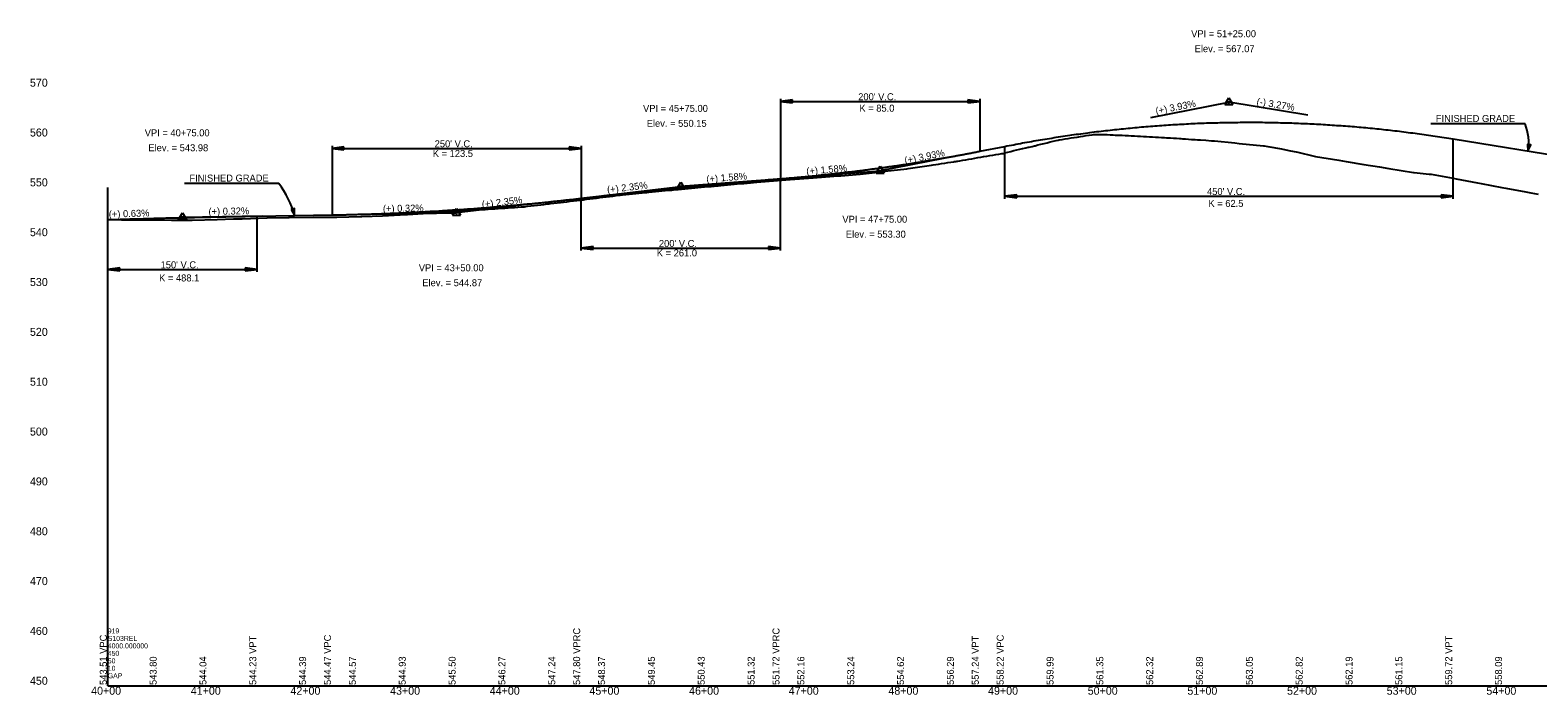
# Model space of a CAD drawing. Extents: x 49922 to 54713, y 49991 to 62800.
# Drawn here: x 49922 to 51435, y 61991 to 62658 of the extents above; entities that cross this region are included whole.
import ezdxf

# ---------------------------------------------------------------- set-up
doc = ezdxf.new("R2010")
doc.units = 0
for name, color, linetype in [('RD_DDB_ElevTX', 7, 'Continuous'), ('RD_DDB_GradeTX', 7, 'Continuous'), ('RD_DDB_Profile_EX', 7, 'Continuous'), ('RD_DDB_Profile_Lbl', 7, 'Continuous'), ('RD_DDB_Profile_PR', 7, 'Continuous'), ('RD_DDB_StaTX', 7, 'Continuous'), ('RD_DDB_StripGrade', 7, 'Continuous'), ('RD_DDB_VCLbl', 7, 'Continuous'), ('RD_GPK_Profile_Cell', 7, 'Continuous'), ('RD_TX_Profile', 7, 'Continuous')]:
    doc.layers.add(name, color=color, linetype=linetype)

msp = doc.modelspace()

# ---------------------------------------------------------------- linework, layer by layer
at = {"layer": 'RD_DDB_GradeTX'}
for p, q in [((51121, 62583.1), (51125, 62589.9)), ((51125, 62589.9), (51129, 62583.1)), ((51046.5, 62569.9), (51125, 62585.3)), ((51121, 62583.1), (51129, 62583.1)), ((51204, 62572.5), (51125, 62585.3)), ((50853.5, 62532), (50775, 62516.5)), ((50695.2, 62510.2), (50775, 62516.5)), ((50771, 62514.2), (50775, 62521.1)), ((50771, 62514.2), (50779, 62514.2)), ((50775, 62521.1), (50779, 62514.2)), ((50495.5, 62491.4), (50575, 62500.7)), ((50571, 62498.4), (50575, 62505.3)), ((50571, 62498.4), (50579, 62498.4)), ((50654.8, 62507), (50575, 62500.7)), ((50575, 62505.3), (50579, 62498.4)), ((50429.5, 62483.7), (50350, 62474.3)), ((50000, 62467.6), (50075, 62469.9)), ((50071, 62467.6), (50075, 62474.5)), ((50071, 62467.6), (50079, 62467.6)), ((50075, 62474.5), (50079, 62467.6)), ((50155, 62471.2), (50075, 62469.9)), ((50270, 62473.1), (50350, 62474.3)), ((50346, 62472), (50350, 62478.9)), ((50346, 62472), (50354, 62472)), ((50350, 62478.9), (50354, 62472))]:
    msp.add_line(p, q, dxfattribs=at)
for centre in [(51125, 62585.3), (50775, 62516.5), (50575, 62500.7), (50075, 62469.9), (50350, 62474.3)]:
    msp.add_circle(centre, 0.529, dxfattribs=at)
at = {"layer": 'RD_DDB_Profile_EX'}
for points in [[(50546.2, 62495.4), (50549.5, 62495.8), (50552.8, 62496.1), (50556.1, 62496.4), (50559.3, 62496.7), (50563.1, 62497.1), (50564, 62497.2), (50565.9, 62497.3), (50569.2, 62497.7), (50572.5, 62498), (50575.8, 62498.3), (50579.1, 62498.6), (50582.3, 62498.9), (50585.6, 62499.2), (50588.2, 62499.4), (50588.9, 62499.5), (50592.2, 62499.8), (50595.5, 62500.1), (50598.8, 62500.4), (50602.1, 62500.7), (50605.4, 62501), (50608.6, 62501.3), (50612.1, 62501.6), (50612.6, 62501.6), (50615.2, 62501.9), (50618.5, 62502.2), (50621.8, 62502.5), (50625.2, 62502.8), (50628.4, 62503.1), (50631.7, 62503.4), (50634.9, 62503.7), (50637.3, 62503.9), (50638.2, 62504), (50641.5, 62504.2), (50644.8, 62504.5), (50651.3, 62505.1), (50659.8, 62505.8), (50684.8, 62507.7), (50707.8, 62509.5), (50732.8, 62511.5), (50735.7, 62511.7), (50754.8, 62513.2), (50779.1, 62516), (50779.8, 62516.1), (50801.9, 62518.7), (50803, 62518.9), (50826.6, 62522.4), (50828.1, 62522.6), (50833.7, 62523.4), (50836.7, 62523.9), (50839.8, 62524.3), (50842.8, 62524.8), (50845.8, 62525.2), (50848.8, 62525.7), (50849.4, 62525.8), (50850.9, 62526), (50851.9, 62526.1), (50852.8, 62526.3), (50854.9, 62526.7), (50857.9, 62527.2), (50860.9, 62527.7), (50863.9, 62528.2), (50867, 62528.7), (50870, 62529.3), (50873, 62529.8), (50876, 62530.3), (50878.7, 62530.8), (50879, 62530.8), (50882.1, 62531.3), (50885.1, 62531.8), (50888.1, 62532.3), (50891.1, 62532.8), (50894.1, 62533.3), (50897.2, 62533.9), (50898.5, 62534.1), (50900.2, 62534.5), (50903.2, 62535.3), (50906.2, 62536), (50909.3, 62536.8), (50912.3, 62537.5), (50915.3, 62538.3), (50917.7, 62538.9), (50918.3, 62539), (50921.3, 62539.7), (50923.5, 62540.2), (50924.4, 62540.4), (50927.4, 62541.1), (50929.9, 62541.7), (50930.4, 62541.8), (50933.4, 62542.6), (50936.4, 62543.3), (50939.5, 62544), (50942.5, 62544.8), (50945.6, 62545.5), (50948.5, 62546.2), (50951.5, 62546.9), (50953.6, 62547.4), (50954.6, 62547.5), (50957.6, 62548), (50960.6, 62548.5), (50963.6, 62549)], [(50963.6, 62549), (50966.7, 62549.5), (50969.2, 62549.9), (50969.7, 62550), (50972.7, 62550.4), (50976, 62550.9), (50978.7, 62551.4), (50981.8, 62551.9), (50984.8, 62552.4), (50987.8, 62552.8), (50989.2, 62553), (50990.8, 62553.1), (50991.5, 62553.1), (50993.8, 62553.1), (50995.4, 62553), (50996.9, 62553), (50999.9, 62553), (51001.8, 62552.9), (51002.9, 62552.9), (51005.9, 62552.7), (51008.9, 62552.6), (51010.7, 62552.5), (51012, 62552.4), (51015, 62552.3), (51018, 62552.2), (51021, 62552), (51024.1, 62551.9), (51026.8, 62551.7), (51027.1, 62551.7), (51030.1, 62551.6), (51033.1, 62551.4), (51035.6, 62551.3), (51036.1, 62551.2), (51039.2, 62551.1), (51042.2, 62550.9), (51045.2, 62550.8), (51048.2, 62550.6), (51051.2, 62550.4), (51051.8, 62550.4), (51054.3, 62550.3), (51057.3, 62550.1), (51060.3, 62549.9), (51062.2, 62549.8), (51063.3, 62549.7), (51066.3, 62549.5), (51069.4, 62549.3), (51072.4, 62549.2), (51075.4, 62549), (51076.8, 62548.9), (51078.4, 62548.8), (51081.5, 62548.6), (51084.5, 62548.4), (51087.5, 62548.1), (51090.5, 62547.9), (51091, 62547.9), (51093.5, 62547.7), (51096.6, 62547.5), (51101.8, 62547.2), (51107.5, 62546.7), (51110.4, 62546.5), (51130.8, 62544.5), (51135.3, 62544), (51159.6, 62541.5), (51160.2, 62541.5), (51164.1, 62541.1), (51177.8, 62538.7), (51185.2, 62537.1), (51194.2, 62535.3), (51210.5, 62531.3), (51211.7, 62531), (51235.2, 62527.1), (51242.6, 62525.9), (51260.2, 62523), (51276, 62520.5), (51285.3, 62518.9), (51310.3, 62514.9), (51310.7, 62514.8), (51325.9, 62513.3), (51328, 62513.1), (51349.9, 62509.1), (51353, 62508.5), (51374.4, 62504.5), (51378, 62503.9), (51398.8, 62500), (51403, 62499.2), (51423, 62495.5), (51428, 62494.5), (51435.2, 62493.2)], [(50000, 62467.6), (50013.9, 62467.5), (50014.6, 62467.5), (50038.9, 62467.3), (50039.6, 62467.3), (50063.9, 62467.1), (50084.2, 62467), (50084.6, 62467), (50109.6, 62467.8), (50126.3, 62468.3), (50134.7, 62468.5), (50159.6, 62469.3), (50160, 62469.3), (50181.3, 62469.9), (50181.9, 62469.9), (50206.3, 62470), (50207, 62470), (50228.9, 62470.1), (50229.9, 62470.1), (50253.9, 62470.9), (50254.9, 62470.9), (50275.6, 62471.5), (50299.4, 62472.9), (50300.6, 62472.9), (50321.7, 62474.1), (50322.7, 62474.1), (50345.8, 62475.6), (50347.7, 62475.8), (50349, 62475.8), (50352.3, 62476.1), (50355.5, 62476.3), (50358.8, 62476.5), (50362.1, 62476.7), (50365.4, 62476.9), (50368, 62477.1), (50368.7, 62477.2), (50370.1, 62477.3), (50372, 62477.4), (50372.5, 62477.5), (50375.3, 62477.7), (50378.6, 62477.9), (50381.8, 62478.1), (50385.1, 62478.3), (50388.4, 62478.5), (50391.7, 62478.8), (50395.1, 62479), (50398.3, 62479.2), (50401.6, 62479.4), (50404.8, 62479.7), (50408.1, 62479.9), (50411.4, 62480.1), (50414.7, 62480.4), (50416.3, 62480.5), (50418, 62480.6), (50419.5, 62480.8), (50421.3, 62481), (50424.6, 62481.4), (50427.9, 62481.8), (50431.1, 62482.1), (50434.4, 62482.5), (50437.7, 62482.9), (50441, 62483.3), (50442.9, 62483.5), (50444.3, 62483.7), (50447.6, 62484), (50450.9, 62484.4), (50454.2, 62484.8), (50457.4, 62485.2), (50460.7, 62485.6), (50464, 62486), (50467.3, 62486.4), (50470.6, 62486.8), (50473.9, 62487.2), (50477.2, 62487.6), (50480.4, 62488), (50483.7, 62488.5), (50486.5, 62488.8), (50487, 62488.9), (50490.3, 62489.3), (50492.3, 62489.5), (50493.6, 62489.7), (50496.9, 62490.1), (50500.2, 62490.5), (50503.5, 62490.9), (50506.7, 62491.3), (50510, 62491.7), (50513.3, 62492.1), (50514.2, 62492.2), (50515.7, 62492.4), (50516.6, 62492.5), (50519.9, 62492.8), (50523.2, 62493.1), (50526.5, 62493.5), (50529.8, 62493.8), (50533, 62494.1), (50536.3, 62494.5), (50539.6, 62494.8), (50540.3, 62494.9), (50540.9, 62494.9), (50542.9, 62495.1), (50546.2, 62495.4)]]:
    msp.add_lwpolyline(points, dxfattribs=at)
at = {"layer": 'RD_DDB_Profile_PR'}
for p, q in [((51350, 62548.6), (51500, 62524.1)), ((50875, 62536.2), (50900, 62541.1)), ((50150, 62471.1), (50225, 62472.3))]:
    msp.add_line(p, q, dxfattribs=at)
for points in [[(50900, 62541.1), (50909, 62542.8), (50918, 62544.5), (50927, 62546.1), (50936, 62547.7), (50945, 62549.1), (50954, 62550.6), (50963, 62551.9), (50972, 62553.2), (50981, 62554.4), (50990, 62555.6), (50999, 62556.6), (51008, 62557.7), (51017, 62558.6), (51026, 62559.5), (51035, 62560.4), (51044, 62561.1), (51053, 62561.8), (51062, 62562.5), (51071, 62563), (51080, 62563.5), (51089, 62564), (51098, 62564.4), (51107, 62564.7), (51116, 62564.9), (51125, 62565.1), (51134, 62565.2), (51143, 62565.3), (51152, 62565.3), (51161, 62565.2), (51170, 62565), (51179, 62564.8), (51188, 62564.6), (51197, 62564.2), (51206, 62563.8), (51215, 62563.4), (51224, 62562.8), (51233, 62562.2), (51242, 62561.6), (51251, 62560.9), (51260, 62560.1), (51269, 62559.2), (51278, 62558.3), (51287, 62557.3), (51296, 62556.3), (51305, 62555.1), (51314, 62554), (51323, 62552.7), (51332, 62551.4), (51341, 62550), (51350, 62548.6)], [(50675, 62508.6), (50679, 62508.9), (50683, 62509.3), (50687, 62509.6), (50691, 62510), (50695, 62510.3), (50699, 62510.7), (50703, 62511.1), (50707, 62511.4), (50711, 62511.8), (50715, 62512.3), (50719, 62512.7), (50723, 62513.1), (50727, 62513.5), (50731, 62514), (50735, 62514.4), (50739, 62514.9), (50743, 62515.4), (50747, 62515.8), (50751, 62516.3), (50755, 62516.8), (50759, 62517.3), (50763, 62517.8), (50767, 62518.4), (50771, 62518.9), (50775, 62519.5), (50779, 62520), (50783, 62520.6), (50787, 62521.2), (50791, 62521.7), (50795, 62522.3), (50799, 62522.9), (50803, 62523.5), (50807, 62524.2), (50811, 62524.8), (50815, 62525.4), (50819, 62526.1), (50823, 62526.8), (50827, 62527.4), (50831, 62528.1), (50835, 62528.8), (50839, 62529.5), (50843, 62530.2), (50847, 62530.9), (50851, 62531.6), (50855, 62532.4), (50859, 62533.1), (50863, 62533.9), (50867, 62534.6), (50871, 62535.4), (50875, 62536.2)], [(50475, 62489), (50479, 62489.5), (50483, 62489.9), (50487, 62490.4), (50491, 62490.8), (50495, 62491.3), (50499, 62491.8), (50503, 62492.2), (50507, 62492.7), (50511, 62493.1), (50515, 62493.5), (50519, 62494), (50523, 62494.4), (50527, 62494.8), (50531, 62495.3), (50535, 62495.7), (50539, 62496.1), (50543, 62496.5), (50547, 62496.9), (50551, 62497.4), (50555, 62497.8), (50559, 62498.2), (50563, 62498.6), (50567, 62499), (50571, 62499.4), (50575, 62499.8), (50579, 62500.2), (50583, 62500.5), (50587, 62500.9), (50591, 62501.3), (50595, 62501.7), (50599, 62502.1), (50603, 62502.4), (50607, 62502.8), (50611, 62503.2), (50615, 62503.5), (50619, 62503.9), (50623, 62504.3), (50627, 62504.6), (50631, 62505), (50635, 62505.3), (50639, 62505.7), (50643, 62506), (50647, 62506.3), (50651, 62506.7), (50655, 62507), (50659, 62507.3), (50663, 62507.7), (50667, 62508), (50671, 62508.3), (50675, 62508.6)], [(50225, 62472.3), (50230, 62472.4), (50235, 62472.5), (50240, 62472.6), (50245, 62472.7), (50250, 62472.9), (50255, 62473), (50260, 62473.1), (50265, 62473.3), (50270, 62473.5), (50275, 62473.6), (50280, 62473.8), (50285, 62474), (50290, 62474.2), (50295, 62474.4), (50300, 62474.7), (50305, 62474.9), (50310, 62475.2), (50315, 62475.4), (50320, 62475.7), (50325, 62476), (50330, 62476.2), (50335, 62476.5), (50340, 62476.9), (50345, 62477.2), (50350, 62477.5), (50355, 62477.8), (50360, 62478.2), (50365, 62478.5), (50370, 62478.9), (50375, 62479.3), (50380, 62479.7), (50385, 62480.1), (50390, 62480.5), (50395, 62480.9), (50400, 62481.3), (50405, 62481.8), (50410, 62482.2), (50415, 62482.7), (50420, 62483.2), (50425, 62483.6), (50430, 62484.1), (50435, 62484.6), (50440, 62485.1), (50445, 62485.7), (50450, 62486.2), (50455, 62486.7), (50460, 62487.3), (50465, 62487.8), (50470, 62488.4), (50475, 62489)], [(50000, 62467.6), (50003, 62467.7), (50006, 62467.8), (50009, 62467.8), (50012, 62467.9), (50015, 62468), (50018, 62468.1), (50021, 62468.2), (50024, 62468.3), (50027, 62468.4), (50030, 62468.5), (50033, 62468.5), (50036, 62468.6), (50039, 62468.7), (50042, 62468.8), (50045, 62468.9), (50048, 62469), (50051, 62469), (50054, 62469.1), (50057, 62469.2), (50060, 62469.3), (50063, 62469.3), (50066, 62469.4), (50069, 62469.5), (50072, 62469.6), (50075, 62469.6), (50078, 62469.7), (50081, 62469.8), (50084, 62469.8), (50087, 62469.9), (50090, 62470), (50093, 62470), (50096, 62470.1), (50099, 62470.2), (50102, 62470.2), (50105, 62470.3), (50108, 62470.4), (50111, 62470.4), (50114, 62470.5), (50117, 62470.5), (50120, 62470.6), (50123, 62470.7), (50126, 62470.7), (50129, 62470.8), (50132, 62470.8), (50135, 62470.9), (50138, 62470.9), (50141, 62471), (50144, 62471), (50147, 62471.1), (50150, 62471.1)]]:
    msp.add_spline(points, degree=3, dxfattribs=at)
at = {"layer": 'RD_DDB_VCLbl'}
for p, q in [((50675, 62588.7), (50675, 62508.6)), ((50687, 62587.7), (50675, 62586.2)), ((50687, 62584.7), (50687, 62587.7)), ((50875, 62586.2), (50863, 62587.7)), ((50863, 62587.7), (50863, 62584.7)), ((50875, 62588.7), (50875, 62536.2)), ((50675, 62586.2), (50875, 62586.2)), ((50675, 62586.2), (50687, 62584.7)), ((50863, 62584.7), (50875, 62586.2)), ((50225, 62541.5), (50225, 62472.3)), ((50475, 62541.5), (50475, 62489)), ((51350, 62488.6), (51350, 62548.6)), ((50237, 62540.5), (50225, 62539)), ((50225, 62539), (50475, 62539)), ((50225, 62539), (50237, 62537.5)), ((50237, 62537.5), (50237, 62540.5)), ((50475, 62539), (50463, 62540.5)), ((50463, 62540.5), (50463, 62537.5)), ((50463, 62537.5), (50475, 62539)), ((50900, 62488.6), (50900, 62541.1)), ((50675, 62436.5), (50675, 62508.6)), ((50475, 62436.5), (50475, 62489)), ((50912, 62492.6), (50900, 62491.1)), ((50900, 62491.1), (51350, 62491.1)), ((50900, 62491.1), (50912, 62489.6)), ((50912, 62489.6), (50912, 62492.6)), ((51350, 62491.1), (51338, 62492.6)), ((51338, 62492.6), (51338, 62489.6)), ((51338, 62489.6), (51350, 62491.1)), ((50000, 62415.1), (50000, 62467.6)), ((50150, 62415.1), (50150, 62471.1)), ((50487, 62440.5), (50475, 62439)), ((50475, 62439), (50675, 62439)), ((50475, 62439), (50487, 62437.5)), ((50487, 62437.5), (50487, 62440.5)), ((50675, 62439), (50663, 62440.5)), ((50663, 62440.5), (50663, 62437.5)), ((50663, 62437.5), (50675, 62439)), ((50012, 62419.1), (50000, 62417.6)), ((50000, 62417.6), (50150, 62417.6)), ((50000, 62417.6), (50012, 62416.1)), ((50012, 62416.1), (50012, 62419.1)), ((50150, 62417.6), (50138, 62419.1)), ((50138, 62419.1), (50138, 62416.1)), ((50138, 62416.1), (50150, 62417.6))]:
    msp.add_line(p, q, dxfattribs=at)
at = {"layer": 'RD_GPK_Profile_Cell'}
for q in [(50000, 62500), (54700, 62000), (50000, 62000)]:
    msp.add_line((50000, 62000), q, dxfattribs=at)
at = {"layer": 'RD_TX_Profile'}
for p, q in [((51422.1, 62563.6), (51327.6, 62563.6)), ((50171.5, 62503.8), (50076.9, 62503.8))]:
    msp.add_line(p, q, dxfattribs=at)
for points in [[(51424.5, 62543.3), (51425, 62536.4), (51428, 62542.7)], [(50184, 62477.8), (50187.5, 62471.7), (50187.5, 62478.7)]]:
    msp.add_lwpolyline(points, close=True, dxfattribs=at)
for centre, radius, start, end in [((51377.8, 62545.2), 48, 349.4125, 22.5386), ((50100.6, 62448.3), 90, 15.067, 38.0243)]:
    msp.add_arc(centre, radius, start, end, dxfattribs=at)

# ---------------------------------------------------------------- texts
at = {"layer": 'RD_DDB_ElevTX'}
for s, p in [('570', (49921.9, 62601)), ('560', (49921.9, 62551)), ('550', (49921.9, 62501)), ('540', (49921.9, 62451)), ('530', (49921.9, 62401)), ('520', (49921.9, 62351)), ('510', (49921.9, 62301)), ('500', (49921.9, 62251)), ('490', (49921.9, 62201)), ('480', (49921.9, 62151)), ('470', (49921.9, 62101)), ('460', (49921.9, 62051)), ('450', (49921.9, 62001))]:
    msp.add_text(s, height=8, dxfattribs=at).set_placement(p)
at = {"layer": 'RD_DDB_GradeTX'}
for s, rotation, p in [('(+) 3.93%', 11.125, (51052.1, 62573.1)), ('(-) 3.27%', 350.727, (51152.4, 62582.9)), ('(+) 3.93%', 11.125, (50800.2, 62523.5)), ('(+) 1.58%', 4.5147, (50600.9, 62504.8)), ('(+) 1.58%', 4.5147, (50701.2, 62512.7)), ('(+) 2.35%', 6.6887, (50501.4, 62494.1)), ('(+) 0.32%', 0.9201, (50276.1, 62475.2)), ('(+) 2.35%', 6.6887, (50375.7, 62479.4)), ('(+) 0.63%', 1.7999, (50001.1, 62469.6)), ('(+) 0.32%', 0.9201, (50101.1, 62472.3))]:
    msp.add_text(s, height=7, rotation=rotation, dxfattribs=at).set_placement(p)
at = {"layer": 'RD_DDB_Profile_Lbl'}
for s, p in [('VPI = 51+25.00', (51087.1, 62650.6)), ('Elev. = 567.07', (51090.6, 62635.6)), ('VPI = 45+75.00', (50537.1, 62575.7)), ('VPI = 40+75.00', (50037.1, 62551.2)), ('Elev. = 550.15', (50540.8, 62560.7)), ('Elev. = 543.98', (50040.7, 62536.2)), ('VPI = 47+75.00', (50737.1, 62464.5)), ('Elev. = 553.30', (50740.6, 62449.5)), ('VPI = 43+50.00', (50312.1, 62415.8)), ('Elev. = 544.87', (50315.6, 62400.8))]:
    msp.add_text(s, height=7, dxfattribs=at).set_placement(p)
at = {"layer": 'RD_DDB_StaTX'}
for s, p in [('40+00', (49983.3, 61991)), ('41+00', (50083.3, 61991)), ('42+00', (50183.3, 61991)), ('43+00', (50283.3, 61991)), ('44+00', (50383.3, 61991)), ('45+00', (50483.3, 61991)), ('46+00', (50583.3, 61991)), ('47+00', (50683.3, 61991)), ('48+00', (50783.3, 61991)), ('49+00', (50883.3, 61991)), ('50+00', (50983.3, 61991)), ('51+00', (51083.3, 61991)), ('52+00', (51183.3, 61991)), ('53+00', (51283.3, 61991)), ('54+00', (51383.3, 61991))]:
    msp.add_text(s, height=8, dxfattribs=at).set_placement(p)
at = {"layer": 'RD_DDB_StripGrade'}
for s, p in [('547.80 VPRC', (50474, 62000.8)), ('547.80 VPRC', (50474, 62000.8)), ('551.72 VPRC', (50674, 62000.8)), ('551.72 VPRC', (50674, 62000.8)), ('543.51 VPC', (49999, 62000.8)), ('544.23 VPT', (50149, 62000.8)), ('544.47 VPC', (50224, 62000.8)), ('557.24 VPT', (50874, 62000.8)), ('558.22 VPC', (50899, 62000.8)), ('559.72 VPT', (51349, 62000.8)), ('543.51', (49999, 62000.8)), ('543.80', (50049, 62000.8)), ('544.04', (50099, 62000.8)), ('544.23', (50149, 62000.8)), ('544.39', (50199, 62000.8)), ('544.57', (50249, 62000.8)), ('544.93', (50299, 62000.8)), ('545.50', (50349, 62000.8)), ('546.27', (50399, 62000.8)), ('547.24', (50449, 62000.8)), ('548.37', (50499, 62000.8)), ('549.45', (50549, 62000.8)), ('550.43', (50599, 62000.8)), ('551.32', (50649, 62000.8)), ('552.16', (50699, 62000.8)), ('553.24', (50749, 62000.8)), ('554.62', (50799, 62000.8)), ('556.29', (50849, 62000.8)), ('558.22', (50899, 62000.8)), ('559.99', (50949, 62000.8)), ('561.35', (50999, 62000.8)), ('562.32', (51049, 62000.8)), ('562.89', (51099, 62000.8)), ('563.05', (51149, 62000.8)), ('562.82', (51199, 62000.8)), ('562.19', (51249, 62000.8)), ('561.15', (51299, 62000.8)), ('559.72', (51349, 62000.8)), ('558.09', (51399, 62000.8))]:
    msp.add_text(s, height=7, rotation=90, dxfattribs=at).set_placement(p)
at = {"layer": 'RD_DDB_VCLbl'}
for s, p in [("200' V.C.", (50753, 62587.4)), ('K = 85.0', (50754.2, 62575.9)), ("250' V.C.", (50328, 62540.2)), ('K = 123.5', (50326.1, 62530.5)), ("450' V.C.", (51103, 62492.3)), ('K = 62.5', (51104.4, 62480.4)), ('K = 261.0', (50550.9, 62430.7)), ("200' V.C.", (50553, 62440.2)), ("150' V.C.", (50053, 62418.8)), ('K = 488.1', (50051.5, 62405.6))]:
    msp.add_text(s, height=7, dxfattribs=at).set_placement(p)
at = {"layer": 'RD_GPK_Profile_Cell'}
for s, p in [('919', (50000, 62052.5)), ('4000.000000', (50000, 62037.5)), ('S103REL', (50000, 62045)), ('450', (50000, 62030)), ('50', (50000, 62022.5)), ('GAP', (50000, 62007.5)), ('10', (50000, 62015))]:
    msp.add_text(s, height=5, dxfattribs=at).set_placement(p)
at = {"layer": 'RD_TX_Profile'}
for p in [(51332.6, 62565.6), (50081.9, 62505.8)]:
    msp.add_text('FINISHED GRADE', height=7, dxfattribs=at).set_placement(p)

doc.saveas('drawing.dxf')
